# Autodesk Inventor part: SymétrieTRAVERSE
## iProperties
Created: 2011-01
Part Number: SymétrieTRAVERSE
Document SubType Name: Modeling
Designer: eric
Density: 1 g/cm^3
Mass: 21.6806 g
Surface Area: 305.415 cm^2
Volume: 21.6806 cm^3
Author: eric
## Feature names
1. Base1
